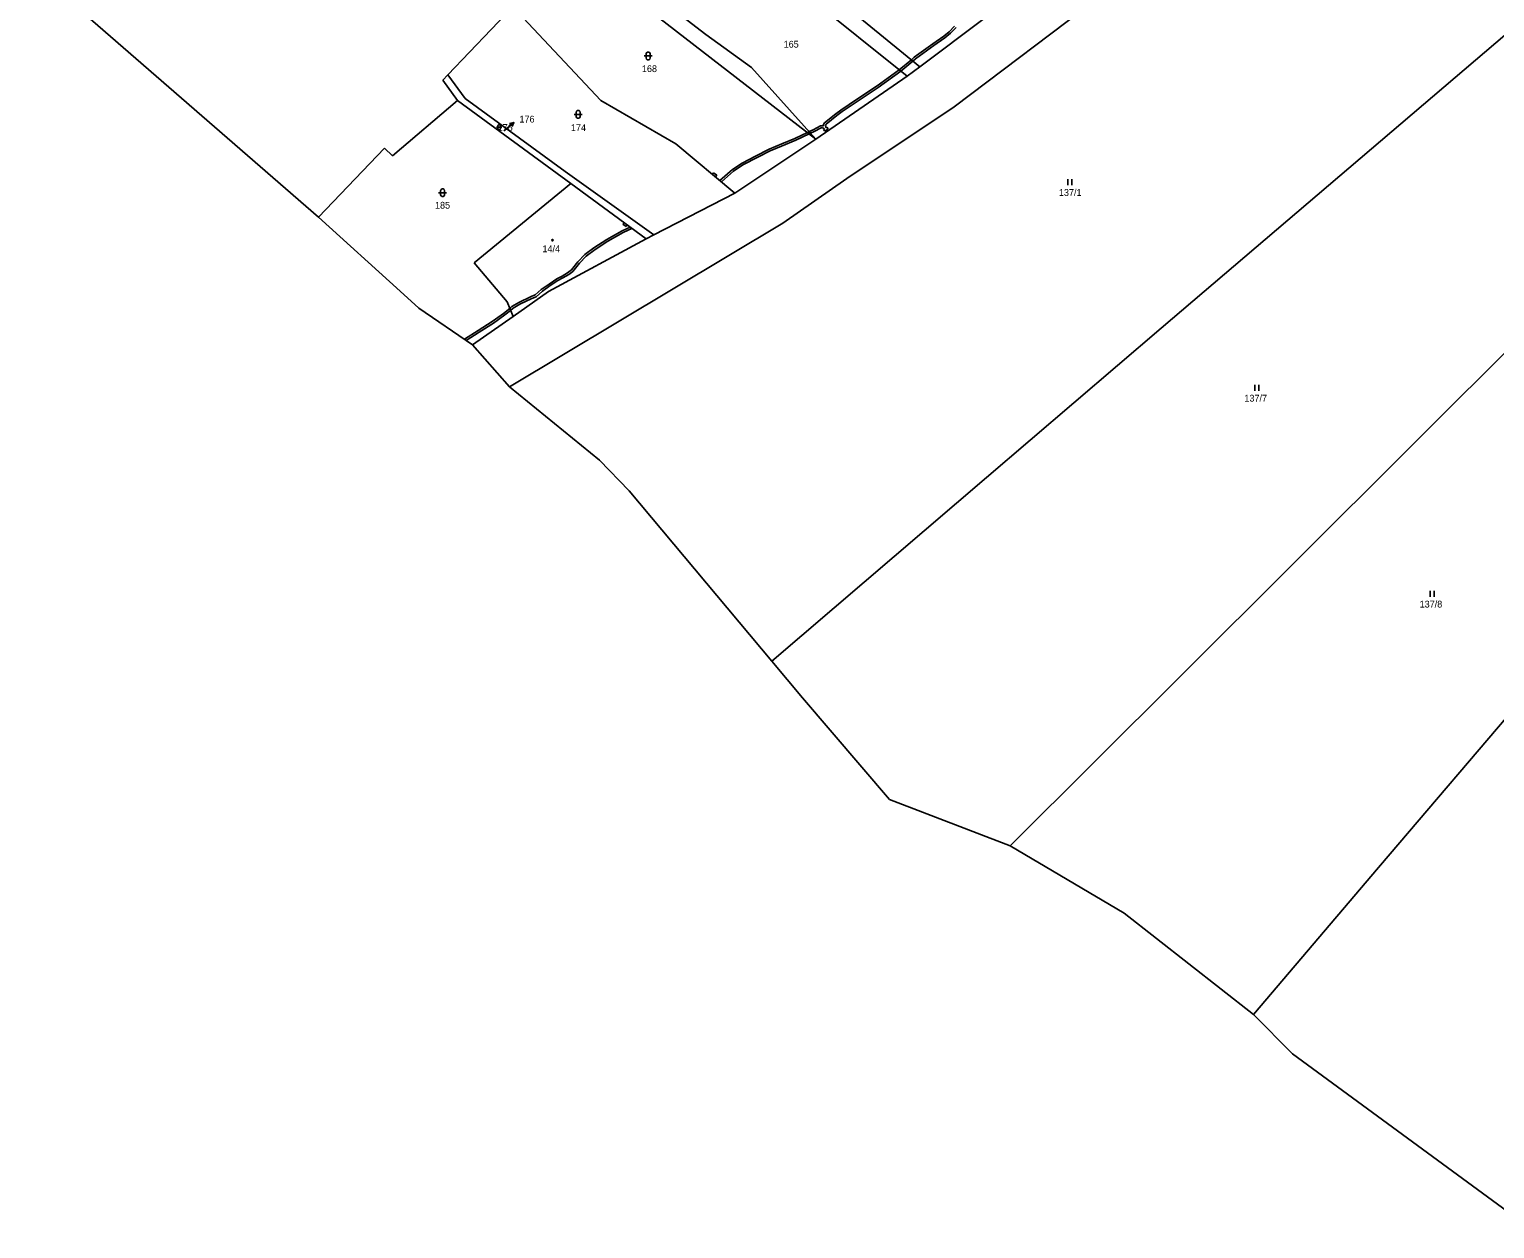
# Model space of a CAD drawing. Extents: x -811039 to -805820, y -1161436 to -1155864.
# Drawn here: x -807196.1 to -806827.8, y -1158672.1 to -1158370.8 of the extents above; entities that cross this region are included whole.
import ezdxf

# ---------------------------------------------------------------- set-up
doc = ezdxf.new("R2010")
doc.units = 0
for name, color, linetype in [('Default', 7, 'Continuous'), ('Hranice kat_území', 7, 'Continuous'), ('Hranice parcel', 7, 'Continuous'), ('Parcelní čísla', 7, 'Continuous'), ('Pop  PČ popisy', 7, 'Continuous'), ('Věcná břemena k části', 7, 'Continuous'), ('Značky kultur', 7, 'Continuous')]:
    doc.layers.add(name, color=color, linetype=linetype)

# ---------------------------------------------------------------- blocks, each defined once
blk = doc.blocks.new('306')
at = {"layer": 'Default'}
for p, q in [((-0.5, 1.5), (-0.5, 0)), ((0.5, 0), (0.5, 1.5))]:
    blk.add_line(p, q, dxfattribs=at)
blk = doc.blocks.new('316')
at = {"layer": 'Default'}
for points in [[(-1, 1), (0.27, 1), (1, 1)], [(-0.5, 1.5), (-0.4, 1.79), (-0.15, 1.97), (0.16, 1.97), (0.41, 1.79), (0.51, 1.5), (0.51, 0.5), (0.41, 0.21), (0.16, 0.03), (-0.15, 0.03), (-0.4, 0.21), (-0.5, 0.5), (-0.5, 1.5)]]:
    blk.add_lwpolyline(points, dxfattribs=at)
blk = doc.blocks.new('NAHRADNI_SYMBOL')
at = {"layer": 'Default'}
blk.add_lwpolyline([(0.09, 0.15), (0.18, 0), (0.09, -0.15), (-0.09, -0.15), (-0.18, 0), (-0.09, 0.15), (0.09, 0.15)], dxfattribs=at)
blk = doc.blocks.new('10292')
at = {"layer": 'Default'}
blk.add_line((0, 3), (0, 0), dxfattribs=at)
blk.add_lwpolyline([(-0.5, 2), (0, 3), (0.5, 2)], dxfattribs=at)

msp = doc.modelspace()

# ---------------------------------------------------------------- linework, layer by layer
at = {"layer": 'Hranice kat_území'}
for p, q in [((-807196.06, -1158354.81), (-807123.37, -1158417.96)), ((-807123.37, -1158417.96), (-807102.87, -1158436.58)), ((-807102.87, -1158436.58), (-807098.17, -1158440.85)), ((-807098.17, -1158440.85), (-807084.68, -1158450.05)), ((-807084.68, -1158450.05), (-807075.39, -1158460.56)), ((-807075.39, -1158460.56), (-807052.75, -1158479.03)), ((-807052.75, -1158479.03), (-807045.33, -1158486.69)), ((-807045.33, -1158486.69), (-807009.51, -1158529.47)), ((-807009.51, -1158529.47), (-807001.78, -1158538.68)), ((-806979.88, -1158564.28), (-807001.78, -1158538.68)), ((-806979.88, -1158564.28), (-806949.58, -1158575.93)), ((-806949.58, -1158575.93), (-806920.92, -1158592.81)), ((-806920.92, -1158592.81), (-806888.43, -1158618.27)), ((-806888.43, -1158618.27), (-806878.64, -1158628.12)), ((-806818.81, -1158672.07), (-806878.64, -1158628.12))]:
    msp.add_line(p, q, dxfattribs=at)
at = {"layer": 'Hranice parcel'}
for p, q in [((-806963.69, -1158390.26), (-806844.14, -1158300.03)), ((-807031.53, -1158331.51), (-806972.28, -1158380.19)), ((-806911.61, -1158445.88), (-806804.42, -1158354.37)), ((-807050.56, -1158358.04), (-806998.39, -1158398.35)), ((-807026.03, -1158372.13), (-807043.91, -1158358.31)), ((-806975.45, -1158382.58), (-807005.5, -1158358.42)), ((-807074.55, -1158365.1), (-807090.87, -1158382.23)), ((-807074.55, -1158365.1), (-807052.44, -1158388.69)), ((-806972.28, -1158380.19), (-806956.16, -1158368.04)), ((-807014.63, -1158380.4), (-807026.03, -1158372.13)), ((-807090.87, -1158382.23), (-807092.11, -1158383.53)), ((-807086.52, -1158388.18), (-807090.87, -1158382.23)), ((-806998.39, -1158398.35), (-807014.63, -1158380.4)), ((-806975.45, -1158382.58), (-806972.28, -1158380.19)), ((-807088.43, -1158388.65), (-807092.11, -1158383.53)), ((-806998.39, -1158398.35), (-806975.45, -1158382.58)), ((-807104.8, -1158402.57), (-807088.43, -1158388.65)), ((-807088.43, -1158388.65), (-807059.99, -1158409.54)), ((-807061.45, -1158406.52), (-807086.52, -1158388.18)), ((-807052.44, -1158388.69), (-807033.6, -1158399.53)), ((-806990.65, -1158408.28), (-806963.69, -1158390.26)), ((-807123.37, -1158417.96), (-807106.83, -1158400.65)), ((-807106.83, -1158400.65), (-807104.8, -1158402.57)), ((-807033.6, -1158399.53), (-807018.76, -1158411.94)), ((-807018.76, -1158411.94), (-806998.39, -1158398.35)), ((-806771.88, -1158398.73), (-806907.04, -1158533.56)), ((-807061.45, -1158406.52), (-807039.1, -1158422.4)), ((-807084.26, -1158429.42), (-807059.99, -1158409.54)), ((-807059.99, -1158409.54), (-807041.08, -1158423.42)), ((-807006.75, -1158419.45), (-806990.65, -1158408.28)), ((-807039.1, -1158422.4), (-807018.76, -1158411.94)), ((-807006.75, -1158419.45), (-807075.39, -1158460.56)), ((-807041.08, -1158423.42), (-807039.1, -1158422.4)), ((-807041.08, -1158423.42), (-807065.6, -1158436.65)), ((-807084.26, -1158429.42), (-807076, -1158439.26)), ((-807065.6, -1158436.65), (-807074.52, -1158442.92)), ((-807076, -1158439.26), (-807074.52, -1158442.92)), ((-807074.52, -1158442.92), (-807084.68, -1158450.05)), ((-806739.35, -1158443.16), (-806857.03, -1158581.38)), ((-806955.55, -1158483.39), (-806911.61, -1158445.88)), ((-807009.51, -1158529.47), (-806955.55, -1158483.39)), ((-806907.04, -1158533.56), (-806949.58, -1158575.93)), ((-806857.03, -1158581.38), (-806888.43, -1158618.27))]:
    msp.add_line(p, q, dxfattribs=at)
at = {"layer": 'Pop  PČ popisy'}
msp.add_line((-807076.82, -1158396.31), (-807076.59, -1158396.12), dxfattribs=at)
at = {"layer": 'Věcná břemena k části'}
for p, q in [((-806964.93, -1158371.42), (-806963.56, -1158369.98)), ((-806963.17, -1158370.29), (-806964.59, -1158371.79)), ((-806973.69, -1158377.81), (-806969.01, -1158374.42)), ((-806968.75, -1158374.85), (-806973.38, -1158378.2)), ((-806969.01, -1158374.42), (-806966.29, -1158372.54)), ((-806965.99, -1158372.95), (-806968.75, -1158374.85)), ((-806966.29, -1158372.54), (-806964.93, -1158371.42)), ((-806964.59, -1158371.79), (-806965.99, -1158372.95)), ((-806977.45, -1158380.97), (-806974.42, -1158378.43)), ((-806974.42, -1158378.43), (-806973.69, -1158377.81)), ((-806973.38, -1158378.2), (-806974.03, -1158378.75)), ((-806983.05, -1158384.98), (-806977.45, -1158380.97)), ((-806977.05, -1158381.29), (-806982.77, -1158385.4)), ((-806974.03, -1158378.75), (-806977.05, -1158381.29)), ((-806987.98, -1158388.27), (-806983.05, -1158384.98)), ((-806982.77, -1158385.4), (-806987.83, -1158388.78)), ((-806992.12, -1158391.06), (-806987.98, -1158388.27)), ((-806987.83, -1158388.78), (-806991.81, -1158391.45)), ((-806996.27, -1158394.3), (-806993.37, -1158392)), ((-806993.11, -1158392.43), (-806995.87, -1158394.62)), ((-806993.37, -1158392), (-806992.12, -1158391.06)), ((-806991.81, -1158391.45), (-806993.11, -1158392.43)), ((-807003.68, -1158398.18), (-807000.54, -1158396.69)), ((-807000.54, -1158396.69), (-807000.09, -1158396.47)), ((-806999.74, -1158396.86), (-807000.1, -1158397.03)), ((-807000.09, -1158396.47), (-806999.1, -1158396)), ((-807000.09, -1158396.47), (-806999.74, -1158396.86)), ((-806999.74, -1158396.86), (-807000.09, -1158396.47)), ((-806998.88, -1158396.45), (-806999.74, -1158396.86)), ((-806999.1, -1158396), (-806997.24, -1158395.07)), ((-806997.12, -1158395.57), (-806998.88, -1158396.45)), ((-806997.24, -1158395.07), (-806996.71, -1158395.07)), ((-806996.77, -1158395.57), (-806997.12, -1158395.57)), ((-806996.45, -1158395.64), (-806996.77, -1158395.57)), ((-806996.71, -1158395.07), (-806996.49, -1158395.12)), ((-806996.57, -1158394.88), (-806996.27, -1158394.3)), ((-806996.49, -1158395.12), (-806996.57, -1158394.88)), ((-806996.46, -1158395.93), (-806996.26, -1158395.8)), ((-806996.18, -1158396.34), (-806996.46, -1158395.93)), ((-806996.26, -1158395.8), (-806996.45, -1158395.64)), ((-806995.35, -1158395.78), (-806996.18, -1158396.34)), ((-806995.87, -1158394.62), (-806996.03, -1158394.92)), ((-806996.03, -1158394.92), (-806995.84, -1158395.5)), ((-806995.84, -1158395.5), (-806995.64, -1158395.37)), ((-806995.64, -1158395.37), (-806995.35, -1158395.78)), ((-807010.17, -1158400.91), (-807006.98, -1158399.56)), ((-807007.02, -1158400.12), (-807009.94, -1158401.35)), ((-807003.46, -1158398.64), (-807007.02, -1158400.12)), ((-807006.98, -1158399.56), (-807003.68, -1158398.18)), ((-807000.1, -1158397.03), (-807003.46, -1158398.64)), ((-807019.39, -1158405.98), (-807016.97, -1158404.37)), ((-807016.97, -1158404.37), (-807013.57, -1158402.64)), ((-807012.97, -1158402.9), (-807016.73, -1158404.81)), ((-807013.57, -1158402.64), (-807010.17, -1158400.91)), ((-807009.94, -1158401.35), (-807012.97, -1158402.9)), ((-807024.43, -1158407.2), (-807024.11, -1158406.82)), ((-807024.24, -1158407.36), (-807024.43, -1158407.2)), ((-807023.85, -1158407.68), (-807024.24, -1158407.36)), ((-807024.11, -1158406.82), (-807023.34, -1158407.46)), ((-807023.66, -1158407.84), (-807023.85, -1158407.68)), ((-807023.34, -1158407.46), (-807023.66, -1158407.84)), ((-807022.55, -1158408.77), (-807019.39, -1158405.98)), ((-807019.08, -1158406.38), (-807022.16, -1158409.09)), ((-807016.73, -1158404.81), (-807019.08, -1158406.38)), ((-807022.16, -1158409.09), (-807022.55, -1158408.77)), ((-807050.92, -1158423.59), (-807047.06, -1158421.37)), ((-807046.82, -1158421.81), (-807050.69, -1158424.03)), ((-807047.06, -1158421.37), (-807045.08, -1158420.48)), ((-807046.9, -1158419.77), (-807046.61, -1158419.36)), ((-807046.09, -1158420.36), (-807046.9, -1158419.77)), ((-807044.62, -1158420.82), (-807046.82, -1158421.81)), ((-807046.61, -1158419.36), (-807046.42, -1158419.5)), ((-807046.42, -1158419.5), (-807045.99, -1158419.81)), ((-807045.8, -1158419.95), (-807046.09, -1158420.36)), ((-807045.99, -1158419.81), (-807045.8, -1158419.95)), ((-807045.08, -1158420.48), (-807044.62, -1158420.82)), ((-807056.44, -1158427.39), (-807054.19, -1158425.67)), ((-807053.91, -1158426.08), (-807056.1, -1158427.76)), ((-807054.19, -1158425.67), (-807050.92, -1158423.59)), ((-807050.69, -1158424.03), (-807053.91, -1158426.08)), ((-807059.82, -1158431.23), (-807058.19, -1158429.19)), ((-807057.81, -1158429.52), (-807059.46, -1158431.59)), ((-807058.19, -1158429.19), (-807056.44, -1158427.39)), ((-807056.1, -1158427.76), (-807057.81, -1158429.52)), ((-807065.45, -1158434.78), (-807063.48, -1158433.44)), ((-807063.48, -1158433.44), (-807062.2, -1158432.8)), ((-807061.98, -1158433.24), (-807063.22, -1158433.88)), ((-807062.2, -1158432.8), (-807060.79, -1158431.98)), ((-807060.5, -1158432.39), (-807061.98, -1158433.24)), ((-807060.79, -1158431.98), (-807059.82, -1158431.23)), ((-807059.46, -1158431.59), (-807060.5, -1158432.39)), ((-807069.96, -1158437.94), (-807068.99, -1158437.52)), ((-807068.99, -1158437.52), (-807067.43, -1158436.18)), ((-807067.12, -1158436.58), (-807068.72, -1158437.95)), ((-807067.43, -1158436.18), (-807065.45, -1158434.78)), ((-807065.14, -1158435.17), (-807067.12, -1158436.58)), ((-807063.22, -1158433.88), (-807065.14, -1158435.17)), ((-807076.87, -1158442.15), (-807075.34, -1158440.89)), ((-807075.34, -1158440.89), (-807074.79, -1158440.43)), ((-807074.5, -1158440.84), (-807075.14, -1158441.38)), ((-807074.79, -1158440.43), (-807073.08, -1158439.37)), ((-807072.84, -1158439.81), (-807074.5, -1158440.84)), ((-807073.08, -1158439.37), (-807069.96, -1158437.94)), ((-807069.82, -1158438.43), (-807072.84, -1158439.81)), ((-807068.72, -1158437.95), (-807069.82, -1158438.43)), ((-807083.31, -1158446.48), (-807079.73, -1158444.17)), ((-807079.46, -1158444.6), (-807082.99, -1158446.87)), ((-807079.73, -1158444.17), (-807076.87, -1158442.15)), ((-807076.56, -1158442.55), (-807079.46, -1158444.6)), ((-807075.14, -1158441.38), (-807076.56, -1158442.55)), ((-807086.72, -1158448.66), (-807083.31, -1158446.48)), ((-807082.99, -1158446.87), (-807086.28, -1158448.96)), ((-807086.28, -1158448.96), (-807086.72, -1158448.66))]:
    msp.add_line(p, q, dxfattribs=at)

# ---------------------------------------------------------------- block references
at = {"layer": 'Pop  PČ popisy', "rotation": -50.14442400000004}
msp.add_blockref('10292', (-807076.59, -1158396.12), dxfattribs=at)
at = {"layer": 'Značky kultur'}
for name, p in [('316', (-807040.58, -1158378.47)), ('316', (-807058.17, -1158393.17)), ('316', (-807092.21, -1158412.84)), ('306', (-806934.57, -1158409.93)), ('NAHRADNI_SYMBOL', (-807064.62, -1158423.74)), ('306', (-806887.65, -1158461.6)), ('306', (-806843.56, -1158513.33))]:
    msp.add_blockref(name, p, dxfattribs=at)
at = {"layer": 'Značky kultur', "xscale": 0.67, "yscale": 0.67}
msp.add_blockref('316', (-807077.98, -1158396.05), dxfattribs=at)

# ---------------------------------------------------------------- texts
at = {"layer": 'Parcelní čísla'}
for s, p in [('165', (-807006.52, -1158375.38)), ('168', (-807042.13, -1158381.53)), ('176', (-807072.9, -1158394.2)), ('176', (-807078.39, -1158396.31)), ('174', (-807059.97, -1158396.34)), ('137/1', (-806937.35, -1158412.63)), ('185', (-807094.12, -1158415.83)), ('14/4', (-807067.12, -1158426.77)), ('137/7', (-806890.74, -1158464.3)), ('137/8', (-806846.71, -1158516.03))]:
    msp.add_text(s, height=1.7, dxfattribs=at).set_placement(p)

doc.saveas('drawing.dxf')
